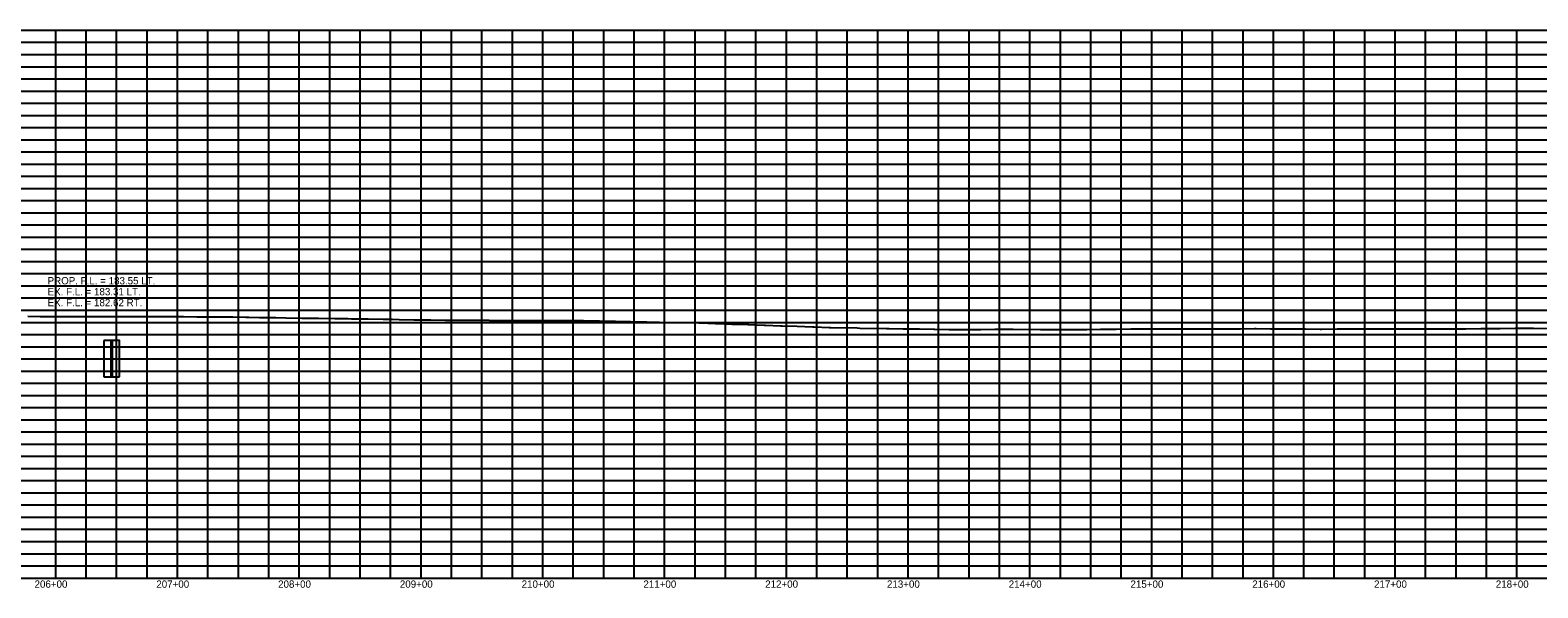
# Model space of a CAD drawing. Extents: x 1399671 to 1408349, y 1930471 to 1933387.
# Drawn here: x 1400903 to 1402141, y 1932071 to 1932529 of the extents above; entities that cross this region are included whole.
import ezdxf

# ---------------------------------------------------------------- set-up
doc = ezdxf.new("R2010")
doc.units = 0
for name, color, linetype in [('R_Drainage', 7, 'Continuous'), ('R_Exist Surface', 7, 'Continuous'), ('R_Grid', 7, 'Continuous'), ('R_Grid Annot', 7, 'Continuous'), ('R_Vert Alg Annot', 7, 'Continuous')]:
    doc.layers.add(name, color=color, linetype=linetype)

msp = doc.modelspace()

# ---------------------------------------------------------------- linework, layer by layer
at = {"layer": 'R_Drainage'}
for p, q in [((1400969.8, 1932273.8), (1400963.8, 1932273.8)), ((1400963.8, 1932273.8), (1400963.8, 1932243.8)), ((1400969.8, 1932243.8), (1400969.8, 1932273.8)), ((1400970.6, 1932273.8), (1400969.8, 1932273.8)), ((1400969.8, 1932273.8), (1400969.8, 1932243.8)), ((1400970.6, 1932243.8), (1400970.6, 1932273.8)), ((1400963.8, 1932243.8), (1400969.8, 1932243.8)), ((1400969.8, 1932243.8), (1400970.6, 1932243.8)), ((1400970.6, 1932243.8), (1400976.6, 1932243.8))]:
    msp.add_line(p, q, dxfattribs=at)
msp.add_lwpolyline([(1400976.6, 1932243.8), (1400976.6, 1932273.8), (1400970.6, 1932273.8), (1400970.6, 1932243.8)], dxfattribs=at)
at = {"layer": 'R_Exist Surface'}
msp.add_lwpolyline([(1400901.4, 1932293.6), (1400911.5, 1932293.4), (1400916.8, 1932293.4), (1400923.8, 1932293.4), (1400929.3, 1932293.3), (1400937.4, 1932293.4), (1400938.7, 1932293.4), (1400946.1, 1932293.4), (1400951.1, 1932293.4), (1400960.1, 1932293.4), (1400960.5, 1932293.4), (1400964.7, 1932293.4), (1400974.1, 1932293.5), (1400978.3, 1932293.4), (1400982.3, 1932293.4), (1400996.5, 1932293.4), (1401002.6, 1932293.4), (1401004.1, 1932293.4), (1401022.2, 1932293.3), (1401025.9, 1932293.3), (1401026.9, 1932293.3), (1401029.2, 1932293.3), (1401040.2, 1932293.2), (1401042.2, 1932293.2), (1401047.7, 1932293.1), (1401053.6, 1932293.1), (1401055.3, 1932293.1), (1401067, 1932293), (1401068.4, 1932293), (1401069.5, 1932293), (1401080.4, 1932292.8), (1401082.7, 1932292.8), (1401091.4, 1932292.7), (1401103.5, 1932292.5), (1401104.9, 1932292.5), (1401113.2, 1932292.3), (1401126.4, 1932292.1), (1401135, 1932292), (1401139.7, 1932292), (1401140, 1932292), (1401153.4, 1932291.8), (1401153.5, 1932291.8), (1401156.8, 1932291.8), (1401164.2, 1932291.7), (1401167.1, 1932291.6), (1401167.1, 1932291.6), (1401178.6, 1932291.5), (1401180.5, 1932291.5), (1401180.7, 1932291.5), (1401193.1, 1932291.2), (1401193.7, 1932291.2), (1401200.4, 1932291.1), (1401206.1, 1932291), (1401218.4, 1932290.8), (1401219.2, 1932290.8), (1401222.2, 1932290.7), (1401231.5, 1932290.6), (1401232.1, 1932290.6), (1401244.1, 1932290.5), (1401247.6, 1932290.5), (1401248.4, 1932290.5), (1401263.8, 1932290.4), (1401264.5, 1932290.4), (1401265.9, 1932290.3), (1401279.9, 1932290.3), (1401280.7, 1932290.2), (1401296, 1932290.1), (1401296.8, 1932290.1), (1401311.4, 1932290.1), (1401312.2, 1932290.1), (1401326.8, 1932290.1), (1401327.6, 1932290.1), (1401342.2, 1932290.1), (1401342.9, 1932290.1), (1401357.6, 1932290.1), (1401369.9, 1932289.8), (1401370.8, 1932289.8), (1401383, 1932289.5), (1401384, 1932289.5), (1401396.2, 1932289.2), (1401408.4, 1932288.9), (1401409, 1932288.9), (1401409.6, 1932288.9), (1401430.6, 1932288.5), (1401431.2, 1932288.5), (1401452.3, 1932288.1), (1401452.9, 1932288.1), (1401453.5, 1932288.1), (1401466.1, 1932287.6), (1401466.8, 1932287.6), (1401479.4, 1932287.2), (1401480.2, 1932287.2), (1401492.6, 1932286.7), (1401493.5, 1932286.7), (1401505.9, 1932286.3), (1401507, 1932286.3), (1401519.5, 1932285.8), (1401520.7, 1932285.8), (1401533.2, 1932285.4), (1401545.7, 1932284.9), (1401546.9, 1932284.9), (1401559.3, 1932284.4), (1401560.6, 1932284.4), (1401582.4, 1932284), (1401584.5, 1932283.9), (1401606.4, 1932283.5), (1401608.5, 1932283.5), (1401620, 1932283.3), (1401621.1, 1932283.3), (1401632.6, 1932283.2), (1401633.6, 1932283.2), (1401645.2, 1932283), (1401646.2, 1932283), (1401657.9, 1932282.8), (1401658.6, 1932282.8), (1401658.8, 1932282.8), (1401670.5, 1932282.8), (1401672.2, 1932282.8), (1401683.8, 1932282.8), (1401695.5, 1932282.9), (1401697.1, 1932282.9), (1401708.8, 1932282.9), (1401710.4, 1932282.9), (1401732.8, 1932282.7), (1401735, 1932282.7), (1401756.7, 1932282.6), (1401758.2, 1932282.6), (1401769.5, 1932282.7), (1401770.9, 1932282.7), (1401782.3, 1932282.9), (1401783.5, 1932282.9), (1401795.1, 1932283), (1401807, 1932283.2), (1401807.9, 1932283.2), (1401819.7, 1932283.2), (1401820.6, 1932283.2), (1401832.3, 1932283.3), (1401833.3, 1932283.3), (1401844.9, 1932283.3), (1401845.9, 1932283.3), (1401847, 1932283.3), (1401858.6, 1932283.3), (1401859.7, 1932283.3), (1401871.4, 1932283.4), (1401883.1, 1932283.4), (1401884.2, 1932283.4), (1401895.9, 1932283.4), (1401897.1, 1932283.4), (1401908.6, 1932283.5), (1401909.9, 1932283.5), (1401921.8, 1932283.4), (1401923, 1932283.4), (1401924.3, 1932283.4), (1401936.2, 1932283.3), (1401937.4, 1932283.3), (1401949.3, 1932283.2), (1401950.5, 1932283.2), (1401962.5, 1932283.1), (1401963.7, 1932283.1), (1401976.4, 1932283.2), (1401977.6, 1932283.2), (1401990.2, 1932283.2), (1402002.9, 1932283.3), (1402004.1, 1932283.3), (1402016.8, 1932283.4), (1402018, 1932283.4), (1402029.7, 1932283.4), (1402030.7, 1932283.4), (1402042.4, 1932283.3), (1402043.3, 1932283.3), (1402055.1, 1932283.3), (1402056, 1932283.3), (1402067.8, 1932283.3), (1402068.7, 1932283.3), (1402081.1, 1932283.4), (1402082.2, 1932283.4), (1402094.5, 1932283.5), (1402095.6, 1932283.5), (1402096.8, 1932283.5), (1402109.1, 1932283.6), (1402110.4, 1932283.6), (1402122.6, 1932283.7), (1402124.1, 1932283.7), (1402136.3, 1932283.7), (1402137.7, 1932283.7), (1402150, 1932283.6)], dxfattribs=at)
at = {"layer": 'R_Grid'}
for p, q in [((1400324.2, 1932528.6), (1407124.2, 1932528.6)), ((1400324.2, 1932528.6), (1407124.2, 1932528.6)), ((1400924.2, 1932078.6), (1400924.2, 1932528.6)), ((1400949.2, 1932078.6), (1400949.2, 1932528.6)), ((1400974.2, 1932078.6), (1400974.2, 1932528.6)), ((1400999.2, 1932078.6), (1400999.2, 1932528.6)), ((1401024.2, 1932078.6), (1401024.2, 1932528.6)), ((1401049.2, 1932078.6), (1401049.2, 1932528.6)), ((1401074.2, 1932078.6), (1401074.2, 1932528.6)), ((1401099.2, 1932078.6), (1401099.2, 1932528.6)), ((1401124.2, 1932078.6), (1401124.2, 1932528.6)), ((1401149.2, 1932078.6), (1401149.2, 1932528.6)), ((1401174.2, 1932078.6), (1401174.2, 1932528.6)), ((1401199.2, 1932078.6), (1401199.2, 1932528.6)), ((1401224.2, 1932078.6), (1401224.2, 1932528.6)), ((1401249.2, 1932078.6), (1401249.2, 1932528.6)), ((1401274.2, 1932078.6), (1401274.2, 1932528.6)), ((1401299.2, 1932078.6), (1401299.2, 1932528.6)), ((1401324.2, 1932078.6), (1401324.2, 1932528.6)), ((1401349.2, 1932078.6), (1401349.2, 1932528.6)), ((1401374.2, 1932078.6), (1401374.2, 1932528.6)), ((1401399.2, 1932078.6), (1401399.2, 1932528.6)), ((1401424.2, 1932078.6), (1401424.2, 1932528.6)), ((1401449.2, 1932078.6), (1401449.2, 1932528.6)), ((1401474.2, 1932078.6), (1401474.2, 1932528.6)), ((1401499.2, 1932078.6), (1401499.2, 1932528.6)), ((1401524.2, 1932078.6), (1401524.2, 1932528.6)), ((1401549.2, 1932078.6), (1401549.2, 1932528.6)), ((1401574.2, 1932078.6), (1401574.2, 1932528.6)), ((1401599.2, 1932078.6), (1401599.2, 1932528.6)), ((1401624.2, 1932078.6), (1401624.2, 1932528.6)), ((1401649.2, 1932078.6), (1401649.2, 1932528.6)), ((1401674.2, 1932078.6), (1401674.2, 1932528.6)), ((1401699.2, 1932078.6), (1401699.2, 1932528.6)), ((1401724.2, 1932078.6), (1401724.2, 1932528.6)), ((1401749.2, 1932078.6), (1401749.2, 1932528.6)), ((1401774.2, 1932078.6), (1401774.2, 1932528.6)), ((1401799.2, 1932078.6), (1401799.2, 1932528.6)), ((1401824.2, 1932078.6), (1401824.2, 1932528.6)), ((1401849.2, 1932078.6), (1401849.2, 1932528.6)), ((1401874.2, 1932078.6), (1401874.2, 1932528.6)), ((1401899.2, 1932078.6), (1401899.2, 1932528.6)), ((1401924.2, 1932078.6), (1401924.2, 1932528.6)), ((1401949.2, 1932078.6), (1401949.2, 1932528.6)), ((1401974.2, 1932078.6), (1401974.2, 1932528.6)), ((1401999.2, 1932078.6), (1401999.2, 1932528.6)), ((1402024.2, 1932078.6), (1402024.2, 1932528.6)), ((1402049.2, 1932078.6), (1402049.2, 1932528.6)), ((1402074.2, 1932078.6), (1402074.2, 1932528.6)), ((1402099.2, 1932078.6), (1402099.2, 1932528.6)), ((1402124.2, 1932078.6), (1402124.2, 1932528.6)), ((1400324.2, 1932518.6), (1407124.2, 1932518.6)), ((1400324.2, 1932508.6), (1407124.2, 1932508.6)), ((1400324.2, 1932498.6), (1407124.2, 1932498.6)), ((1400324.2, 1932488.6), (1407124.2, 1932488.6)), ((1400324.2, 1932478.6), (1407124.2, 1932478.6)), ((1400324.2, 1932468.6), (1407124.2, 1932468.6)), ((1400324.2, 1932458.6), (1407124.2, 1932458.6)), ((1400324.2, 1932448.6), (1407124.2, 1932448.6)), ((1400324.2, 1932438.6), (1407124.2, 1932438.6)), ((1400324.2, 1932428.6), (1407124.2, 1932428.6)), ((1400324.2, 1932418.6), (1407124.2, 1932418.6)), ((1400324.2, 1932408.6), (1407124.2, 1932408.6)), ((1400324.2, 1932398.6), (1407124.2, 1932398.6)), ((1400324.2, 1932388.6), (1407124.2, 1932388.6)), ((1400324.2, 1932378.6), (1407124.2, 1932378.6)), ((1400324.2, 1932368.6), (1407124.2, 1932368.6)), ((1400324.2, 1932358.6), (1407124.2, 1932358.6)), ((1400324.2, 1932348.6), (1407124.2, 1932348.6)), ((1400324.2, 1932338.6), (1407124.2, 1932338.6)), ((1400324.2, 1932328.6), (1407124.2, 1932328.6)), ((1400324.2, 1932318.6), (1407124.2, 1932318.6)), ((1400324.2, 1932308.6), (1407124.2, 1932308.6)), ((1400324.2, 1932298.6), (1407124.2, 1932298.6)), ((1400324.2, 1932288.6), (1407124.2, 1932288.6)), ((1400324.2, 1932278.6), (1407124.2, 1932278.6)), ((1400324.2, 1932268.6), (1407124.2, 1932268.6)), ((1400324.2, 1932258.6), (1407124.2, 1932258.6)), ((1400324.2, 1932248.6), (1407124.2, 1932248.6)), ((1400324.2, 1932238.6), (1407124.2, 1932238.6)), ((1400324.2, 1932228.6), (1407124.2, 1932228.6)), ((1400324.2, 1932218.6), (1407124.2, 1932218.6)), ((1400324.2, 1932208.6), (1407124.2, 1932208.6)), ((1400324.2, 1932198.6), (1407124.2, 1932198.6)), ((1400324.2, 1932188.6), (1407124.2, 1932188.6)), ((1400324.2, 1932178.6), (1407124.2, 1932178.6)), ((1400324.2, 1932168.6), (1407124.2, 1932168.6)), ((1400324.2, 1932158.6), (1407124.2, 1932158.6)), ((1400324.2, 1932148.6), (1407124.2, 1932148.6)), ((1400324.2, 1932138.6), (1407124.2, 1932138.6)), ((1400324.2, 1932128.6), (1407124.2, 1932128.6)), ((1400324.2, 1932118.6), (1407124.2, 1932118.6)), ((1400324.2, 1932108.6), (1407124.2, 1932108.6)), ((1400324.2, 1932098.6), (1407124.2, 1932098.6)), ((1400324.2, 1932088.6), (1407124.2, 1932088.6)), ((1400324.2, 1932078.6), (1407124.2, 1932078.6))]:
    msp.add_line(p, q, dxfattribs=at)

# ---------------------------------------------------------------- texts
at = {"layer": 'R_Grid Annot'}
for s, p in [('206+00', (1400906.8, 1932070.6)), ('207+00', (1401006.8, 1932070.6)), ('208+00', (1401106.8, 1932070.6)), ('209+00', (1401206.8, 1932070.6)), ('210+00', (1401306.8, 1932070.6)), ('211+00', (1401406.8, 1932070.6)), ('212+00', (1401506.8, 1932070.6)), ('213+00', (1401606.8, 1932070.6)), ('214+00', (1401706.8, 1932070.6)), ('215+00', (1401806.8, 1932070.6)), ('216+00', (1401906.8, 1932070.6)), ('217+00', (1402006.8, 1932070.6)), ('218+00', (1402106.8, 1932070.6))]:
    msp.add_text(s, height=6, dxfattribs=at).set_placement(p)
at = {"layer": 'R_Vert Alg Annot'}
for s, p in [('PROP. F.L. = 183.55 LT.', (1400917.5, 1932319.8)), ('EX. F.L. = 183.31 LT.', (1400917.5, 1932310.8)), ('EX. F.L. = 182.62 RT.', (1400917.5, 1932301.8))]:
    msp.add_text(s, height=6, dxfattribs=at).set_placement(p)

doc.saveas('drawing.dxf')
